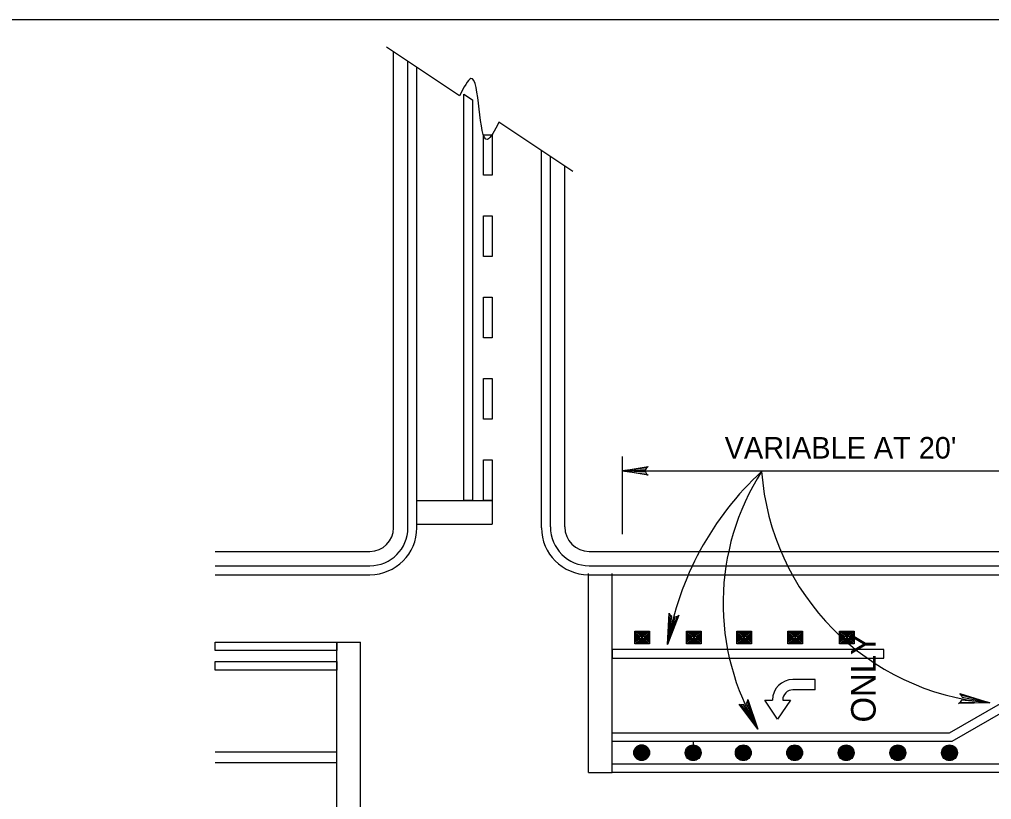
# Model space of a CAD drawing. Extents: x 639362 to 641108, y 298458 to 299646.
# Drawn here: x 639788.7 to 639923.9, y 298928.7 to 299037.2 of the extents above; entities that cross this region are included whole.
import ezdxf

# ---------------------------------------------------------------- set-up
doc = ezdxf.new("R2010")
doc.units = 0
for name, color, linetype in [('1', 7, 'Continuous'), ('2', 7, 'Continuous'), ('3', 7, 'Continuous')]:
    doc.layers.add(name, color=color, linetype=linetype)

# ---------------------------------------------------------------- blocks, each defined once
blk = doc.blocks.new('RARROW')
at = {"layer": '3'}
blk.add_lwpolyline([(-2.2695, 0.285), (-2.184875, 0.12075), (0, 0), (-2.2695, 0.285), (-2.38575, 0.384625), (0, 0), (-2.183125, -0.108), (-2.262875, -0.2705), (0, 0), (-2.38575, -0.379125), (-2.262875, -0.2705)], dxfattribs=at)

msp = doc.modelspace()

# ---------------------------------------------------------------- linework, layer by layer
at = {"layer": '1'}
msp.add_line((639403.27, 299037.19), (640189.27, 299037.19), dxfattribs=at)
at = {"layer": '2'}
for p, q in [((639849.91, 299026.56), (639839.75, 299033.33)), ((639840.75, 298966.48), (639840.75, 299032.67)), ((639842.75, 298966.48), (639842.75, 299031.33)), ((639843.98, 298966.48), (639843.98, 299030.51)), ((639850.53, 298970.29), (639850.53, 299026.79)), ((639850.53, 299026.79), (639851.73, 299025.99)), ((639851.73, 299025.99), (639851.73, 298970.29)), ((639865.68, 299016.04), (639855.4, 299022.9)), ((639861.32, 298966.48), (639861.32, 299018.96)), ((639862.55, 298966.6), (639862.55, 299018.13)), ((639864.55, 298966.6), (639864.55, 299016.8)), ((639872.53, 298976.4), (639872.53, 298965.6)), ((639872.53, 298974.4), (639941.89, 298974.4)), ((639843.98, 298970.29), (639854.47, 298970.29)), ((639851.73, 298970.29), (639850.53, 298970.29)), ((639854.47, 298970.29), (639854.47, 298966.99)), ((639843.97, 298966.99), (639854.47, 298966.99)), ((639815.93, 298963.2), (639837.47, 298963.2)), ((639867.95, 298963.2), (639989.83, 298963.2)), ((639815.93, 298961.2), (639837.47, 298961.2)), ((639867.95, 298961.2), (639989.83, 298961.2)), ((639815.93, 298959.96), (639837.47, 298959.96)), ((639867.83, 298932.45), (639867.83, 298960.1)), ((639867.83, 298959.96), (639989.83, 298959.96)), ((639871.13, 298932.45), (639871.13, 298960.1)), ((639874.29, 298950.34), (639874.29, 298952.12)), ((639874.29, 298952.12), (639876.33, 298952.12)), ((639874.47, 298950.52), (639874.47, 298951.94)), ((639874.47, 298951.94), (639876.16, 298951.94)), ((639874.65, 298950.7), (639874.65, 298951.76)), ((639874.65, 298951.76), (639875.98, 298951.76)), ((639875.98, 298951.76), (639875.98, 298950.7)), ((639876.16, 298951.94), (639876.16, 298950.52)), ((639876.33, 298952.12), (639876.33, 298950.34)), ((639881.47, 298950.34), (639881.47, 298952.12)), ((639881.47, 298952.12), (639883.51, 298952.12)), ((639881.65, 298950.52), (639881.65, 298951.94)), ((639881.65, 298951.94), (639883.34, 298951.94)), ((639881.83, 298950.7), (639881.83, 298951.76)), ((639881.83, 298951.76), (639883.16, 298951.76)), ((639883.16, 298951.76), (639883.16, 298950.7)), ((639883.34, 298951.94), (639883.34, 298950.52)), ((639883.51, 298952.12), (639883.51, 298950.34)), ((639888.48, 298950.34), (639888.48, 298952.12)), ((639888.48, 298952.12), (639890.52, 298952.12)), ((639888.66, 298950.52), (639888.66, 298951.94)), ((639888.66, 298951.94), (639890.34, 298951.94)), ((639888.83, 298950.7), (639888.83, 298951.76)), ((639888.83, 298951.76), (639890.16, 298951.76)), ((639890.16, 298951.76), (639890.16, 298950.7)), ((639890.34, 298951.94), (639890.34, 298950.52)), ((639890.52, 298952.12), (639890.52, 298950.34)), ((639895.57, 298950.34), (639895.57, 298952.12)), ((639895.57, 298952.12), (639897.61, 298952.12)), ((639895.75, 298950.52), (639895.75, 298951.94)), ((639895.75, 298951.94), (639897.43, 298951.94)), ((639895.93, 298950.7), (639895.93, 298951.76)), ((639895.93, 298951.76), (639897.26, 298951.76)), ((639897.26, 298951.76), (639897.26, 298950.7)), ((639897.43, 298951.94), (639897.43, 298950.52)), ((639897.61, 298952.12), (639897.61, 298950.34)), ((639902.75, 298950.34), (639902.75, 298952.12)), ((639902.75, 298952.12), (639904.79, 298952.12)), ((639902.93, 298950.52), (639902.93, 298951.94)), ((639902.93, 298951.94), (639904.61, 298951.94)), ((639903.11, 298950.7), (639903.11, 298951.76)), ((639903.11, 298951.76), (639904.43, 298951.76)), ((639904.43, 298951.76), (639904.43, 298950.7)), ((639904.61, 298951.94), (639904.61, 298950.52)), ((639904.79, 298952.12), (639904.79, 298950.34)), ((639918.03, 298937.96), (639941.89, 298951.73)), ((639815.93, 298949.39), (639815.93, 298950.59)), ((639815.93, 298950.59), (639832.85, 298950.59)), ((639832.85, 298922.95), (639832.85, 298950.59)), ((639832.85, 298950.59), (639836.15, 298950.59)), ((639832.85, 298950.59), (639832.85, 298949.39)), ((639836.15, 298922.95), (639836.15, 298950.59)), ((639876.16, 298950.52), (639874.47, 298950.52)), ((639875.98, 298950.7), (639874.65, 298950.7)), ((639874.83, 298951.58), (639875.8, 298951.58)), ((639874.83, 298950.88), (639874.83, 298951.58)), ((639875.8, 298950.88), (639874.83, 298950.88)), ((639875, 298951.05), (639875, 298951.41)), ((639875, 298951.41), (639875.62, 298951.41)), ((639875.62, 298951.05), (639875, 298951.05)), ((639875.18, 298951.23), (639875.45, 298951.23)), ((639875.62, 298951.41), (639875.62, 298951.05)), ((639875.8, 298951.58), (639875.8, 298950.88)), ((639883.34, 298950.52), (639881.65, 298950.52)), ((639883.16, 298950.7), (639881.83, 298950.7)), ((639882.01, 298951.58), (639882.98, 298951.58)), ((639882.01, 298950.88), (639882.01, 298951.58)), ((639882.98, 298950.88), (639882.01, 298950.88)), ((639882.18, 298951.05), (639882.18, 298951.41)), ((639882.18, 298951.41), (639882.8, 298951.41)), ((639882.8, 298951.05), (639882.18, 298951.05)), ((639882.36, 298951.23), (639882.63, 298951.23)), ((639882.8, 298951.41), (639882.8, 298951.05)), ((639882.98, 298951.58), (639882.98, 298950.88)), ((639890.34, 298950.52), (639888.66, 298950.52)), ((639890.16, 298950.7), (639888.83, 298950.7)), ((639889.01, 298951.58), (639889.99, 298951.58)), ((639889.01, 298950.88), (639889.01, 298951.58)), ((639889.99, 298950.88), (639889.01, 298950.88)), ((639889.19, 298951.05), (639889.19, 298951.41)), ((639889.19, 298951.41), (639889.81, 298951.41)), ((639889.81, 298951.05), (639889.19, 298951.05)), ((639889.36, 298951.23), (639889.63, 298951.23)), ((639889.81, 298951.41), (639889.81, 298951.05)), ((639889.99, 298951.58), (639889.99, 298950.88)), ((639897.43, 298950.52), (639895.75, 298950.52)), ((639897.26, 298950.7), (639895.93, 298950.7)), ((639896.1, 298951.58), (639897.08, 298951.58)), ((639896.1, 298950.88), (639896.1, 298951.58)), ((639897.08, 298950.88), (639896.1, 298950.88)), ((639896.28, 298951.05), (639896.28, 298951.41)), ((639896.28, 298951.41), (639896.9, 298951.41)), ((639896.9, 298951.05), (639896.28, 298951.05)), ((639896.46, 298951.23), (639896.72, 298951.23)), ((639896.9, 298951.41), (639896.9, 298951.05)), ((639897.08, 298951.58), (639897.08, 298950.88)), ((639904.61, 298950.52), (639902.93, 298950.52)), ((639904.43, 298950.7), (639903.11, 298950.7)), ((639903.28, 298951.58), (639904.26, 298951.58)), ((639903.28, 298950.88), (639903.28, 298951.58)), ((639904.26, 298950.88), (639903.28, 298950.88)), ((639903.46, 298951.05), (639903.46, 298951.41)), ((639903.46, 298951.41), (639904.08, 298951.41)), ((639904.08, 298951.05), (639903.46, 298951.05)), ((639903.64, 298951.23), (639903.9, 298951.23)), ((639904.08, 298951.41), (639904.08, 298951.05)), ((639904.26, 298951.58), (639904.26, 298950.88)), ((639942.21, 298950.53), (639918.36, 298936.76)), ((639832.85, 298949.39), (639815.93, 298949.39)), ((639908.88, 298949.57), (639871.13, 298949.57)), ((639871.13, 298949.57), (639871.13, 298948.35)), ((639876.33, 298950.34), (639874.29, 298950.34)), ((639883.51, 298950.34), (639881.47, 298950.34)), ((639890.52, 298950.34), (639888.48, 298950.34)), ((639897.61, 298950.34), (639895.57, 298950.34)), ((639904.79, 298950.34), (639902.75, 298950.34)), ((639908.88, 298948.35), (639908.88, 298949.57)), ((639815.93, 298946.66), (639815.93, 298947.86)), ((639815.93, 298947.86), (639832.85, 298947.86)), ((639832.85, 298947.86), (639832.85, 298946.66)), ((639871.13, 298948.35), (639908.88, 298948.35)), ((639832.85, 298946.66), (639815.93, 298946.66)), ((639899.35, 298945.37), (639896.27, 298945.37)), ((639899.35, 298943.94), (639899.35, 298945.37)), ((639899.35, 298943.94), (639896.27, 298943.94)), ((639894.14, 298939.85), (639892.36, 298942.52)), ((639892.36, 298942.52), (639893.42, 298942.52)), ((639895.91, 298942.52), (639894.14, 298939.85)), ((639894.85, 298942.52), (639895.91, 298942.52)), ((639871.13, 298936.76), (639871.13, 298937.96)), ((639871.13, 298937.96), (639918.03, 298937.96)), ((639918.36, 298936.76), (639871.13, 298936.76)), ((639882.4, 298936.76), (639882.4, 298935.19)), ((639815.93, 298935.33), (639832.85, 298935.33)), ((639815.93, 298933.83), (639832.85, 298933.83)), ((639871.13, 298932.45), (639871.13, 298933.65)), ((639871.13, 298933.65), (639989.73, 298933.65)), ((639867.83, 298932.45), (639871.13, 298932.45)), ((639989.83, 298932.45), (639871.13, 298932.45))]:
    msp.add_line(p, q, dxfattribs=at)
for points in [[(639853.27, 299021.16), (639854.47, 299021.16), (639854.47, 299015.51), (639853.27, 299015.51)], [(639853.27, 299009.86), (639854.47, 299009.86), (639854.47, 299004.2), (639853.27, 299004.2)], [(639853.27, 298998.55), (639854.47, 298998.55), (639854.47, 298992.9), (639853.27, 298992.9)], [(639853.27, 298987.25), (639854.47, 298987.25), (639854.47, 298981.59), (639853.27, 298981.59)], [(639853.27, 298975.94), (639854.47, 298975.94), (639854.47, 298970.29), (639853.27, 298970.29)]]:
    msp.add_lwpolyline(points, close=True, dxfattribs=at)
for points in [[(639880.16, 298954.15), (639879.84, 298954.06), (639878.81, 298950.25), (639880.16, 298954.15), (639880.38, 298954.31), (639878.81, 298950.25), (639879.44, 298954.14), (639879.18, 298954.34), (639878.81, 298950.25), (639879.04, 298954.6), (639879.18, 298954.34)], [(639889.95, 298942.34), (639889.75, 298942.07), (639891.39, 298938.49), (639889.95, 298942.34), (639890.01, 298942.61), (639891.39, 298938.49), (639889.39, 298941.88), (639889.06, 298941.87), (639891.39, 298938.49), (639888.79, 298941.97), (639889.06, 298941.87)], [(639919.66, 298943.22), (639919.77, 298942.9), (639923.63, 298942.14), (639919.66, 298943.22), (639919.48, 298943.42), (639923.63, 298942.14), (639919.71, 298942.49), (639919.53, 298942.23), (639923.63, 298942.14), (639919.28, 298942.06), (639919.53, 298942.23)]]:
    msp.add_lwpolyline(points, dxfattribs=at)
for centre, radius in [((639875.24, 298935.2), 1.1), ((639875.24, 298935.2), 1.02), ((639875.24, 298935.2), 0.946), ((639875.24, 298935.2), 0.868), ((639875.24, 298935.2), 0.789), ((639875.24, 298935.2), 0.711), ((639875.24, 298935.2), 0.633), ((639875.24, 298935.2), 0.554), ((639875.24, 298935.2), 0.476), ((639875.24, 298935.2), 0.398), ((639875.24, 298935.2), 0.32), ((639882.4, 298935.19), 1.1), ((639882.4, 298935.19), 1.02), ((639882.4, 298935.19), 0.946), ((639882.4, 298935.19), 0.868), ((639882.4, 298935.19), 0.789), ((639882.4, 298935.19), 0.711), ((639882.4, 298935.19), 0.633), ((639882.4, 298935.19), 0.554), ((639882.4, 298935.19), 0.476), ((639882.4, 298935.19), 0.398), ((639882.4, 298935.19), 0.32), ((639889.36, 298935.19), 1.1), ((639889.36, 298935.19), 1.02), ((639889.36, 298935.19), 0.946), ((639889.36, 298935.19), 0.868), ((639889.36, 298935.19), 0.789), ((639889.36, 298935.19), 0.711), ((639889.36, 298935.19), 0.633), ((639889.36, 298935.19), 0.554), ((639889.36, 298935.19), 0.476), ((639889.36, 298935.19), 0.398), ((639889.36, 298935.19), 0.32), ((639896.5, 298935.19), 1.1), ((639896.5, 298935.19), 1.02), ((639896.5, 298935.19), 0.946), ((639896.5, 298935.19), 0.868), ((639896.5, 298935.19), 0.789), ((639896.5, 298935.19), 0.711), ((639896.5, 298935.19), 0.633), ((639896.5, 298935.19), 0.554), ((639896.5, 298935.19), 0.476), ((639896.5, 298935.19), 0.398), ((639896.5, 298935.19), 0.32), ((639903.67, 298935.19), 1.1), ((639903.67, 298935.19), 1.02), ((639903.67, 298935.19), 0.946), ((639903.67, 298935.19), 0.868), ((639903.67, 298935.19), 0.789), ((639903.67, 298935.19), 0.711), ((639903.67, 298935.19), 0.633), ((639903.67, 298935.19), 0.554), ((639903.67, 298935.19), 0.476), ((639903.67, 298935.19), 0.398), ((639903.67, 298935.19), 0.32), ((639910.85, 298935.19), 1.1), ((639910.85, 298935.19), 1.02), ((639910.85, 298935.19), 0.946), ((639910.85, 298935.19), 0.868), ((639910.85, 298935.19), 0.789), ((639910.85, 298935.19), 0.711), ((639910.85, 298935.19), 0.633), ((639910.85, 298935.19), 0.554), ((639910.85, 298935.19), 0.476), ((639910.85, 298935.19), 0.398), ((639910.85, 298935.19), 0.32), ((639918.03, 298935.19), 1.1), ((639918.03, 298935.19), 1.02), ((639918.03, 298935.19), 0.946), ((639918.03, 298935.19), 0.868), ((639918.03, 298935.19), 0.789), ((639918.03, 298935.19), 0.711), ((639918.03, 298935.19), 0.633), ((639918.03, 298935.19), 0.554), ((639918.03, 298935.19), 0.476), ((639918.03, 298935.19), 0.398), ((639918.03, 298935.19), 0.32), ((639875.24, 298935.2), 0.241), ((639875.24, 298935.2), 0.163), ((639875.24, 298935.2), 0.0846), ((639882.4, 298935.19), 0.241), ((639882.4, 298935.19), 0.163), ((639882.4, 298935.19), 0.0846), ((639889.36, 298935.19), 0.241), ((639889.36, 298935.19), 0.163), ((639889.36, 298935.19), 0.0846), ((639896.5, 298935.19), 0.241), ((639896.5, 298935.19), 0.163), ((639896.5, 298935.19), 0.0846), ((639903.67, 298935.19), 0.241), ((639903.67, 298935.19), 0.163), ((639903.67, 298935.19), 0.0846), ((639910.85, 298935.19), 0.241), ((639910.85, 298935.19), 0.163), ((639910.85, 298935.19), 0.0846), ((639918.03, 298935.19), 0.241), ((639918.03, 298935.19), 0.163), ((639918.03, 298935.19), 0.0846)]:
    msp.add_circle(centre, radius, dxfattribs=at)
for centre, radius, start, end in [((639920.86, 298942.97), 42.67, 132.7254, 170.1774), ((639920.64, 298955.99), 34.08, 147.4602, 210.8991), ((639926.61, 298976.8), 34.79, 184.0856, 265.0963), ((639867.95, 298966.6), 5.4, 180, 270), ((639867.95, 298966.6), 3.4, 180, 270), ((639837.47, 298966.48), 5.28, 270, 0), ((639837.47, 298966.48), 6.52, 270, 0), ((639837.47, 298966.48), 3.28, 270, 0), ((639867.83, 298966.48), 6.52, 180, 270), ((639896.27, 298942.52), 2.85, 90, 180), ((639896.27, 298942.52), 1.42, 90, 180)]:
    msp.add_arc(centre, radius, start, end, dxfattribs=at)
msp.add_spline([(639855.4, 299022.9), (639853.79, 299020.49), (639851.51, 299028.97), (639849.91, 299026.56)], degree=3, dxfattribs=at)

# ---------------------------------------------------------------- block references
at = {"layer": '2', "xscale": 1.5089217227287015, "yscale": 1.5711553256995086, "rotation": 180}
msp.add_blockref('RARROW', (639872.53, 298974.4), dxfattribs=at)

# ---------------------------------------------------------------- texts
at = {"layer": '2'}
msp.add_text("VARIABLE AT 20'", height=3, dxfattribs=at).set_placement((639886.78, 298976.11))
msp.add_text('ONLY', height=3.414, rotation=90, dxfattribs=at).set_placement((639907.76, 298939.4))

doc.saveas('drawing.dxf')
